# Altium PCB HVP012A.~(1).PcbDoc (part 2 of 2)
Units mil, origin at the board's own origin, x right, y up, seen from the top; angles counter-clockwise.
Board outline 2249 x 2178 mil, 4 copper layers (Top Layer, MidLayer1, MidLayer2, Bottom Layer), stack 61.2 mil thick; 92 components, 29 nets, 189 pads, 191 vias.
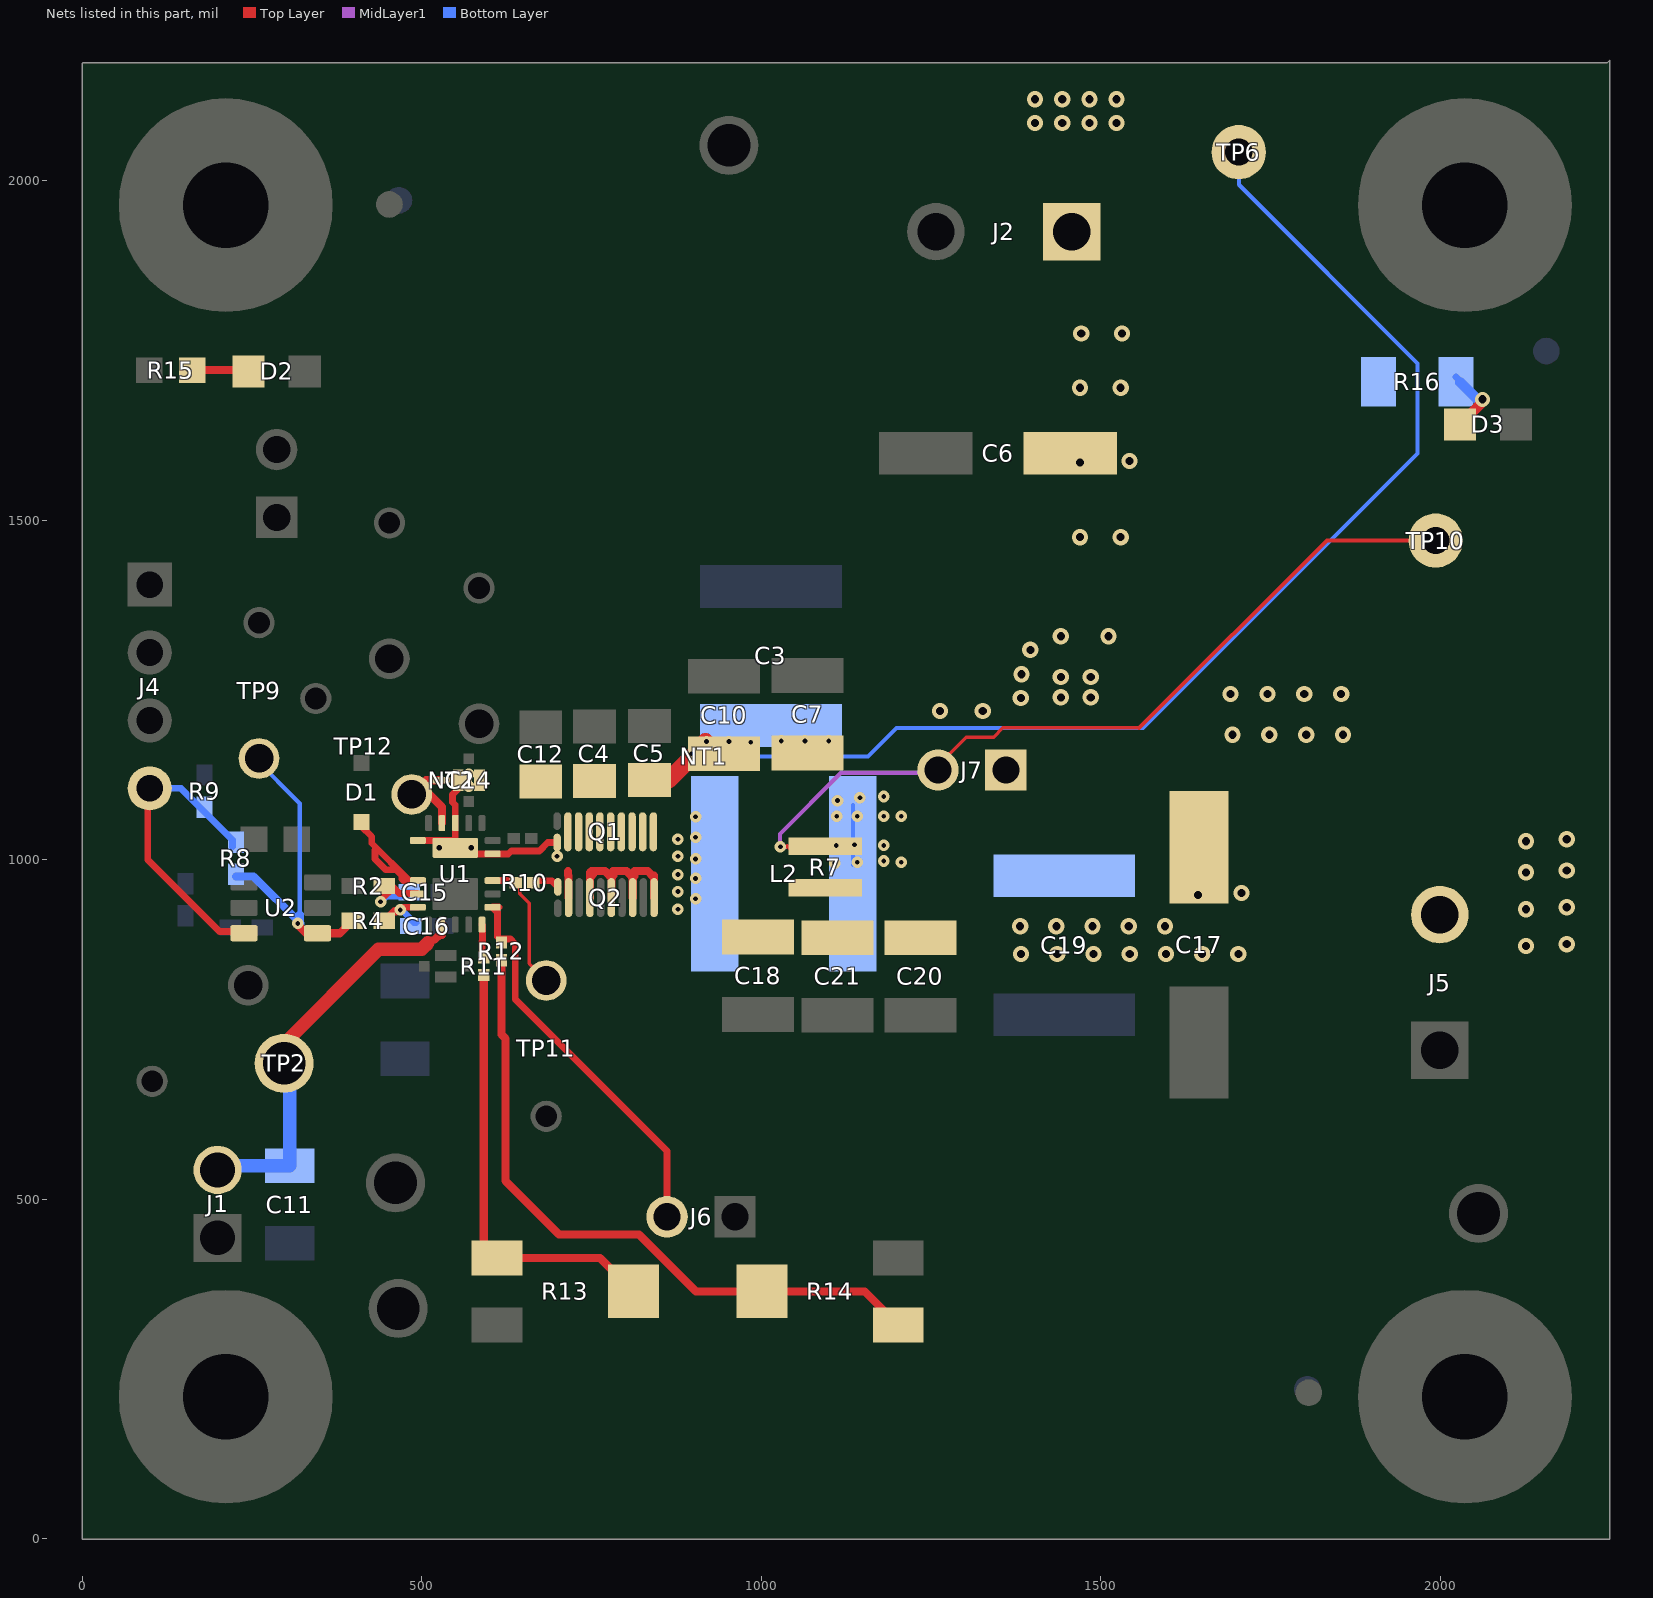
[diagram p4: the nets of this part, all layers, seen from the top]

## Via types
v1: diameter 24, hole 12, Top Layer to Bottom Layer, tented both sides, 110 vias
v2: diameter 17, hole 7, Top Layer to Bottom Layer, tented both sides, 71 vias
v3: diameter 22, hole 12, Top Layer to Bottom Layer, tented both sides, 6 vias
v4: diameter 19.68, hole 7.87, Top Layer to Bottom Layer, 4 vias

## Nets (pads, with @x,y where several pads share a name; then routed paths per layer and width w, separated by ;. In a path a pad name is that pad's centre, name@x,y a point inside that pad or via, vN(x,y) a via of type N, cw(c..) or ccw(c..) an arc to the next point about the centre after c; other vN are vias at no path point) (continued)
HS2: C14.3 L2.1 NT2.2 Q1.2 Q1.4 Q1.6 Q1.8 Q1.10 Q2.3 Q2.5 Q2.7 Q2.9 Q2.11 U1.9 U1.13 U1.16 U1.21@549,1017.39 | length 659.3
  Top Layer w10: U1.16@493.88,1028.21 U1.21@549,1028.21 ; C14.3@553.25,1117 553.25,1104.25 545,1096 545,1084.63 549,1080.63 U1.13@549,1053.8 U1.21@549,1028.21 ; Q1.2@699.13,1025.21 685.26,1025.21 672.78,1012.73 631.73,1012.73 627,1008 626.47,1008.53 U1.9@604.12,1008.53 557.86,1008.53 U1.21@549,1017.39 U1.21@549,1028.21
  Top Layer w12: 715,983 715,977.01 715.88,976.13 Q2.3@715.88,944 ; Q2.5@747.38,944 747.38,976.13 ; Q2.7@778.87,944 778.87,976.13 ; Q2.9@810.37,944 810.37,976.13 ; Q2.11@841.87,944 841.87,976.48 841.51,976.13 839.41,976.13 832.5,983.04 812.83,983.04 812.83,976.13 810.37,976.13 ; 747.38,976.13 749.83,976.13 749.83,976.48 ; 747.38,976.13 747.73,976.48 749.83,976.48 ; 747.38,976.13 747.38,980.99 748,981.61 749.83,979.78 ; 749.83,976.48 749.83,979.78 ; 749.83,976.48 750.19,976.48 750.19,979.43 ; 749.83,979.78 749.83,983.04 750.19,983.04 ; 749.83,979.78 750.19,979.43 ; 750.19,979.43 750.19,983.04 ; 750.19,979.43 751.66,977.95 751.66,983.04 ; 750.19,983.04 751.66,983.04 ; 751.66,983.04 769.51,983.04 776.06,976.48 ; 776.06,976.48 781.33,976.48 ; 776.06,976.48 776.42,976.13 ; 776.42,976.13 778.87,976.13 ; 776.42,976.13 778.87,976.13 ; 778.87,976.13 781.33,976.13 781.33,976.48 ; 781.33,976.48 781.33,983.04 781.68,983.04 ; 781.33,976.48 781.68,976.48 781.68,983.04 ; 781.68,983.04 801.01,983.04 807.56,976.48 ; 807.56,976.48 810.37,976.48 810.37,976.13 ; 807.56,976.48 807.91,976.13 810.37,976.13
  Bottom Layer w6: v2@564,1126 v2@566,1124
  other v2: 877,927 903,942.39 877,953 903,972.39 877,978 903,1001 699,1005 877,1005 877,1030 903,1033 903,1063 569,1108 569,1126
  other v4: 525.38,1017.39 572.62,1017.39
K_VIN: NT1.2 TP6.1 | length 1773.7
  Bottom Layer w6: NT1.2@930,1152 1157,1152 1199,1194 1562,1194 1966,1598 1966,1731 1703,1994 TP6.1@1703,2042
LGATE: Q2.1 R10.2 | length 39
  Top Layer w10: R10.2@664.99,969 690.92,969 Q2.1@700.13,959.79
LO: R10.1 TP11.1 U1.8 | length 197.6
  Top Layer w5: R10.1@638.01,966 644,960.01 644,950 658,936 658,847 TP11.1@683,822
  Top Layer w10: U1.8@604.12,969.16 638.85,969.16 R10.1@639.01,969
NetC11_2: C11.2 J1.2 TP2.1 U1.2 | length 600.6
  Top Layer w10: U1.2@529.21,904.2 U1.2@529.21,904.62
  Top Layer w12: 508.8,877.39 512.42,881 ; 518.78,882.22 525.79,889.22 529.31,889.22 U1.2@529.31,904.2
  Top Layer w20: TP2.1@297,700 297,729 436,868 499.42,868 508.8,877.39
  Bottom Layer w20: J1.2@199,539 209.09,549.09 C11.2@305,549.09 305,692 TP2.1@297,700
NetC15_2: C15.2 R2.2 U1.18 | length 145.5
  Top Layer w10: v2@440,939 440,941 R2.2@458,959 ; R2.2@444.62,961 456,961 R2.2@458,959 ; 466,951 R2.2@458,959 ; 467,950 493.35,950 U1.18@493.88,949.47
  Bottom Layer w10: v2(439,938) 447,946 468.57,946 C15.2@472.57,950 ; C15.2@467,950 C15.2@472.57,950 ; C15.2@477.62,950 C15.2@472.57,950 ; C15.2@488.38,951 473.57,951 C15.2@472.57,950
NetC16_1: C16.1 R4.2 U1.19 | length 92.4
  Top Layer w10: R4.2@444.62,910 459.62,925 462,922.62 465,925.62 v2@465,927 ; v2@469,926 472.79,929.79 U1.19@493.88,929.79
  Bottom Layer w10: v2@465,923.32 v2@465,927 ; v2@468,928 489,907 C16.1@491.38,907
  other v2: 468,926
NetD1_2: D1.2 U1.17 | length 189.4
  Top Layer w10: D1.2@410,1049.8 426,1033.8 426,1024.16 481,969.16 472.71,969.16 470.37,971.5 470.37,976.95 462.32,985 447,985 431,1001 431,1014
NetD2_1: D2.1 R15.2 | length 79.7
  Top Layer w12: R15.2@161.5,1721 232.66,1721 D2.1@238.66,1715
NetD3_1: D3.1 R16.2 | length 100.9
  Top Layer w10: v3@2060,1678 v3(2062,1678)
  Top Layer w15: D3.1@2028.66,1641 v3@2060,1672.34
  Bottom Layer w10: R16.2@2023.09,1711 2030,1704.09 R16.2@2029,1703.09 ; v3@2054.09,1678 v3(2062,1678)
  Bottom Layer w15: R16.2@2029,1703.09 v3@2054.09,1678
NetJ6_2: J6.2 R12.2 U1.6 | length 582.1
  Top Layer w10: U1.6@604.01,930.21 U1.6@612.92,930.21 ; R12.2@611.42,886.58 611.42,922.48 U1.6@604.12,929.79 U1.6@613.26,929.79 ; R12.2@617,882.96 630.24,882.96 637.24,875.96 637.24,794.52 861,570.75 J6.2@861,474
NetJ7_2: J7.2 L2.2 R7.1 TP10.1 | length 1282.8
  Top Layer w5: v2(1028,1019) 1036.49,1019 1037.74,1020.26 R7.1@1041,1017 ; J7.2@1260,1132 1253,1132 1301.5,1180.5 1341.95,1180.5 1355.45,1194 1556.02,1194
  Top Layer w6: 1556.02,1194 1832.71,1470 TP10.1@1993,1470
  MidLayer1 w6: v2@1035,1018 1027,1026 1027,1038 1117,1128 J7.2@1259,1128
  Bottom Layer w6: L2.2@1134.57,992 1134.57,1022 L2.2@1134.57,1080.57
  other v2: 1108,995 1141,996 1206,996 1180,998 1110,1021 1180,1021 1137,1022 1111,1064 1141,1064 1180,1064 1206,1064 1112,1087 1145,1091 1180,1093
NetNT2_1: NT2.1 TP12.1 U1.14 | length 128.5
  Top Layer w12: NT2.1@529,1117 506,1117 TP12.1@485,1096 511,1096 529.31,1077.69 U1.14@529.31,1053.8
NetR11_1: R11.1 R13.1 R13.2 | length 644.1
  Top Layer w12: R11.1@591,828.04 591,432.82 R13.1@610.61,413.21 762.18,413.21 R13.2@811.39,364
NetR11_2: R11.2 U1.5 | length 47.8
  Top Layer w10: U1.5@588.37,904.2 589,903.57 589,879.66 588.37,879.03 588.37,860.59 R11.2@591,857.96
NetR12_1: R12.1 R14.1 R14.2 | length 994.8
  Top Layer w12: R12.1@617,853.04 617,742.32 623,736.32 623,527 702,448 819.72,448 903.72,364 R14.2@1000.61,364 1152.18,364 R14.1@1201.39,314.79
PWM: R4.1 R8.2 TP9.1 U2.4 | length 491.9
  Top Layer w12: v2@316,905 329.4,891.6 U2.4@346.13,891.6 378.98,891.6 R4.1@397.38,910
  Bottom Layer w6: TP9.1@254,1149 320,1083 320,919
  Bottom Layer w12: R8.2@226,975.38 251.91,975.38 v2@320,907.28 ; v2(317,906) 321.28,906 v2@320,907.28 ; 320,919 v2@320,907.28
PWM_IN: J4.4 R8.1 R9.2 U2.3 | length 449.2
  Top Layer w10: J4.4@96,1099 96,1000 202,894 235.46,894 U2.3@237.87,891.6
  Bottom Layer w10: J4.4@99,1105 145,1105 221,1029 R8.1@221,1019
VIN: C3.1 C4.1 C5.1 C6.1 C7.1 C10.1 C12.1 J2.1 NT1.1 Q1.3 Q1.5 Q1.7 Q1.9 Q1.11 R16.1 | length 110.8
  Top Layer w10: C5.1@835,1117 863.12,1117 C5.1@866,1117
  Top Layer w25: C5.1@863.12,1117 917.41,1171.29 C10.1@917.41,1174.32
  other v1: 1263,1219 1326,1219 1382,1238 1441,1239 1485,1239 1441,1269 1485,1269 1383,1273 1396,1309 1441,1329 1511,1329 1469,1475 1529,1475 1469,1585 1542,1587 1469,1695 1529,1695 1471,1775 1531,1775 1403,2085 1443,2085 1483,2085 1523,2085 1403,2120 1443,2120 1483,2120 1523,2120
  other v2: 897.07,1155.9 984.07,1172.9 919.07,1173.9 952.07,1173.9 1029.07,1174.9 1064.07,1174.9 1099.07,1174.9
VOUT: C17.1 C18.1 C19.1 C20.1 C21.1 J5.2 J7.1 R7.2
  other v1: 1382.33,861 1435.67,861 1489,861 1542.33,861 1595.67,861 1649,861 1702.33,861 2126,872.71 2186,875.57 1381,902 1434.33,902 1487.67,902 1541,902 1594.33,902 2126,927 2186,929.86 1642.67,948 1707,951 2126,981.29 2186,984.14 2126,1027.14 2186,1030 1693.71,1184 1748,1184 1802.29,1184 1856.57,1184 1690.86,1244 1745.14,1244 1799.43,1244 1853.71,1244
pads on no net: FID1.1 FID2.1 FID3.1 FID4.1 FID5.1 FID6.1 H1.1 H2.1 H3.1 H4.1 H5.0 H6.0 H7.0 H8.0 SH-J1.0 U1.1 U1.20@530.3,949.47 U1.20@567.7,949.47 U1.21@530.3,1017.39 U1.21@567.7,1017.39

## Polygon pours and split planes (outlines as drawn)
HS2 on Bottom Layer "HS2_L04_P014" (solid, remove dead copper, pour order 14): 912,1075 882,1045 873,1045 871,1043 871,914 912,876
GND on Bottom Layer "GND_L04_P102" (solid, remove dead copper, pour order 102): 2164.33,41.8 122.33,41.8 22.33,141.8 28.33,147.8 28.33,2075.8 28.33,2077.8 101.33,2150.8 2055.33,2150.8 2234.33,1971.8 2234.33,110.8
HS2 on Bottom Layer "HS2_L04_P078" (solid, remove dead copper, pour order 78): 520,1204 532.96,1172.96 590,1155 631,1080 704,1073 704,982.06 491.65,998 443.21,1077.98 359.33,1130.33 359.33,1204
NetJ7_2 on Bottom Layer "NETJ7_2_L04_P039" (solid, pour order 39): 1099,865 1098,864 1098,734 1106,726 1169,726 1173,730 1255,859 1249,1149 1177,1139 1098,1137
VIN on Bottom Layer "Bottom Layer-No Net 7" (solid, pour order 76): 1386.49,2144 1961,2144 1961,1563.67 1934.95,1563.67 1550.44,1194.15 1541.57,1185.62 917.42,1185.62 911,1192.28 911,1230 956.33,1230 1313.99,1304.19 1317.45,1304.19 1384.55,1368.68 1386.49,1370.54
VOUT on Bottom Layer "Bottom Layer-No Net 6" (solid, pour order 42): 1871,1479 2246,1479 2246,819.43 1256,819.43 1256,1171.3 1551.61,1171.3 1561,1169
HS2 on Bottom Layer "HS2_L04_P104" (solid, remove dead copper, pour order 104): 866,914 926,914 926,1074 921,1079 866,1079
HS2 on Bottom Layer "HS2_L04_P022" (solid, pour order 22): 895,898 895,732 899,728 960,728 966,734 966,834 964,836 964,902
HS2 on MidLayer1 "HS2_L02_P016" (solid, remove dead copper, pour order 16): 520,1204 532.96,1172.96 590,1155 631,1080 704,1073 704,982.06 491.65,998 443.21,1077.98 359.33,1130.33 359.33,1204
GND on MidLayer1 "GND_L02_P082" (solid, remove dead copper, pour order 82): 2154,39 112,39 12,139 18,145 18,2073 18,2075 91,2148 2045,2148 2224,1969 2224,108
HB2 on Top Layer "HB2_L01_P092" (solid, remove dead copper, pour order 92): 582,1138 553,1109 425,1109 392,1142 392,1157 424,1189 427,1192 531,1192 554,1169 573,1169 573,1167 587,1153
NetD1_2 on Top Layer "NETD1_2_L01_P090" (solid, remove dead copper, pour order 90): 386.5,1035.5 427,995 461,961 496,961 503,968 503,978 459,1019 435,1070 392,1070 390,1072
LGATE on Top Layer "LGATE_L01_P023" (solid, pour order 23): 656,974 656,944 661,939 671,929 699.35,929 701,929 706,934 704,976 659.22,977.22
HGATE on Top Layer "HGATE_L01_P024" (solid, pour order 24): 653,1024 654.21,1025.21 701,1025.21 701,1074 667,1074 652,1059 652,1039
HS2 on Top Layer "HS2_L01_P059" (solid, remove dead copper, pour order 59): 628.05,1033.74 859.92,1044.98 900,1065 913,1060.46 913,893.02 882.19,910 820.48,944 624.53,947.6
GND on Top Layer "Top Layer-No Net 1" (solid, pour order 28): 386,2040 870.39,2040 870.39,2151 1361,2151 1361,1442.42 1090.76,1249.76 866.37,1235.5 858,1171 641,1171 641,1299 386,1684
GND on Top Layer "Top Layer-No Net 9" (solid, remove dead copper, pour order 49): 31,779 518.78,882.22 1315.36,266.34 1724,266.34 1724,-1 31,-1
VOUT on Top Layer "Top Layer-No Net 2" (solid, pour order 27): 2201,1479 1871,1479 1561,1169 1541,1169 1277,1169 1246,969 946,969 946,859 2201,842
VIN on Top Layer "Top Layer-No Net" (solid, pour order 29): 1381,2152 1381,1438.77 1239.07,1302.37 1136.32,1247.31 888,1227 888,1165 829.3,1141.2 657,1139.05 657,1090.12 681.83,1081.42 712.65,1057 877.07,1057 967,1126 1139.79,1138.79 1309,1181 1341,1188.87 1532.38,1188.87 1853,1497 1853,2152
GND on Top Layer "Top Layer-No Net 4" (solid, pour order 35): 2253.16,344.84 2253.16,329 1304.43,317.34 675.28,735.25 676.78,942.76 805.53,944.61 986,813.05 2251.68,813.05
NetJ7_2 on Top Layer "NETJ7_2_L01_P094" (solid, remove dead copper, pour order 94): 1081,989 1216,989 1221,994 1221,1079 1216,1084 1203,1097 1089,1097 1076,1084 1076,999 1086,989
no net on Bottom Solder "NONET_L-01_P-001" (solid): 1099,865 1098,864 1098,734 1106,726 1169,726 1173,730 1173,859
no net on Bottom Solder "NONET_L-01_P-001" (solid): 902,894 902,896 864,934 821,934 820,933 820,1049 821,1048 868,1048 872,1048 896,1072 909,1072 910,1073 922,1061 922,893
no net on Bottom Solder "NONET_L-01_P-001" (solid): 896,861 895,860 895,730 903,722 966,722 970,726 970,855
no net on Bottom Paste "NONET_L-01_P-001" (solid): 1099,865 1098,864 1098,734 1106,726 1169,726 1173,730 1173,859
no net on Bottom Paste "NONET_L-01_P-001" (solid): 895,875 894,874 894,744 902,736 965,736 969,740 969,869
HS2 on MidLayer2 "HS2_L03_P015" (solid, remove dead copper, pour order 15): 520,1204 532.96,1172.96 590,1155 631,1080 704,1073 704,982.06 491.65,998 443.21,1077.98 359.33,1130.33 359.33,1204
GND on MidLayer2 "GND_L03_P017" (solid, remove dead copper, pour order 17): 2154,39 112,39 12,139 18,145 18,2073 18,2075 91,2148 2045,2148 2224,1969 2224,108

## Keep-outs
Keep-Out Layer:
  the board outline again, w25
  text ".Layer_Name" at -322,-1089.49 h60

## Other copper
Top Layer:
  rectangle net NetJ6_2: 606,919 631,929
  rectangle net HS2: 470,1024 495,1034
  text ".Layer_Name" at -322,-1089.49 h60
MidLayer1:
  pour cut-out: 871,1065 870,1066 870,1162 1193,1162 1195,1160 1195,799.35 1196.35,798 872,798 869,801 869,903 871,902.42
MidLayer2:
  pour cut-out: 871,1065 870,1066 870,1162 1193,1162 1195,1160 1195,799.35 1196.35,798 872,798 869,801 869,903 871,902.42
Bottom Layer:
  pour cut-out: 926.36,1079 870,1079 870,1162 1101,1162 1101,798 982,801 962,883 900,883 869,801 872,887.92 921,887.92
  text ".Layer_Name" at -322,-1089.49 h60

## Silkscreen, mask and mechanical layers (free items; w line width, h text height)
Top Overlay:
  lines w10: 370,836 465,741 ; 371,990 374,1172 ; 371,1160 373,1160 513,1300 ; 372,831 372,870 ; 465,735 1174,732 ; 521,1301 521,1408 524,1411 ; 521,1306 548,1306 ; 525,1414 552,1414 ; 525,1415 508,1432 508,1469 520,1481 829,1481 846,1464 846,1423 834,1411 ; 616,1412 834,1412 ; 617,1307 1068,1306 ; 1129,1299 1129,1241 1185,1185 1185,929
  text "-" at 1066,2009 h80
  text "+" at 1571,2009 h80
  text "EN(HI)" at 31,1616 h30
  text "GND" at 29.27,1569 h30
  text "GND" at 29.5,1520.46 h30 r359.79
  text "PWM(LI)" at 32,1477 h30
  text "14 x 20mm" at 521,1424 h72.83
  text "+" at 2132,1062 h80 r90
  text "-" at 2153,540 h80 r90
  text "HVP006 A" at 1380,125 h40
  text "LMG1210EVM-012" at 1330,46 h40
  text ".Layer_Name" at -322,-1089.49 h60
Bottom Overlay:
  text ".Layer_Name" at -322,-1089.49 h60
Top Paste:
  text ".Layer_Name" at -322,-1089.49 h60
Bottom Paste:
  text ".Layer_Name" at -322,-1089.49 h60
Top Solder:
  rectangle: 523,1065 536,1082
  rectangle: 543,1064 556,1081
  rectangle: 562,1066 575,1083
  region: 630,1022 630,1035 613,1035 613,1022
  region: 626,1002 626,1015 609,1015 609,1002
  region: 628,963 628,976 611,976 611,963
  region: 628,943 628,956 611,956 611,943
  region: 630,918 630,931 610,931 610,918
  region: 575,896 562,896 562,879 575,879
  region: 555,896 542,896 542,879 555,879
  region: 535.32,896 522.32,896 522.32,879 535.32,879
  region: 468,936.21 468,923.21 485,923.21 485,936.21
  region: 468,955.89 468,942.89 485,942.89 485,955.89
  region: 468,976 468,963 485,963 485,976
  region: 466,1034.21 466,1021.21 483,1021.21 483,1034.21
  text ".Layer_Name" at -322,-1089.49 h60
  text ".Layer_Name" at -322,-1089.49 h60
Bottom Solder:
  text ".Layer_Name" at -322,-1089.49 h60
Drill Guide:
  text ".Layer_Name" at -322,-1089.49 h60
M1 Board Outline:
  lines w10: 1,-1 2236,-1
  lines w25: 1,-1 0,2173 1,2174 2246,2174 2249,2177 2251,4
  text ".Layer_Name" at -322,-1089.49 h60
M2 Board Dimensions:
  rectangle: -899.5,-516.5 -774.5,-391.5
  rectangle: -774.5,-641.5 -399.5,-516.5
  lines w7: -899.5,-516.5 100.5,-516.5 ; -774.5,-641.5 -774.5,-391.5 ; -649.5,-641.5 -649.5,-391.5 ; -399.5,-641.5 -399.5,-391.5 ; -149.5,-641.5 -149.5,-391.5 ; -899.5,-641.5 100.5,-641.5 100.5,-391.5 -899.5,-391.5 -899.5,-641.5
  lines w10: -899.5,-706.5 -899.5,-686.5 ; -839.5,-716.5 -899.5,-696.5 ; -839.5,-676.5 -899.5,-696.5 ; -675.42,-696.5 -899.5,-696.5 ; -123.58,-696.5 100.5,-696.5 ; 40.5,-716.5 100.5,-696.5 ; 40.5,-676.5 100.5,-696.5 ; 100.5,-706.5 100.5,-686.5
  text "1000 (mil)" at -665.42,-732.49 h60
  text ".Layer_Name" at -322,-1089.49 h60
M3 3D STEP Top:
  text ".Layer_Name" at -322,-1089.49 h60
M4 3D STEP Bottom:
  text ".Layer_Name" at -322,-1089.49 h60
M5 Assembly Top:
  lines w10: -1191,-1161.17 5409,-1161.17 ; -1191,-957.83 5411,-957.83 ; -1191,-754.5 -1191,-1364.5 2814,-1364.5 5411,-1364.5 5411,-754.5 -1190.5,-754.5 -1190.5,-1364.5 385,-1364.5 ; 1274,-1364.5 1274,-754.5 ; 2541,-957.83 2541,-754.5 ; 3381,-957.83 3381,-754.5 ; 4003,-1371 4003,-1168.17
  text "COMPONENTS MARKED 'DNP' SHOULD NOT BE POPULATED." at 254.5,-549.5 h60
  text "ASSEMBLY VARIANT:" at 254,-665 h60
  text ".VariantName" at 1290,-665 h60
  text "PCB VIEWED FROM TOP SIDE" at -1127.5,-886.67 h60
  text "BOARD #:" at 1349,-886.67 h60
  text ".PRJ_Number" at 1894.5,-886.67 h60
  text "REV:" at 2739,-886.67 h60
  text ".PCB_Rev" at 3030.5,-886.67 h60
  text "SVN REV:" at 3577,-886.67 h60
  text ".VersionControl_RevNumber" at 4083,-886.67 h60
  text "IGNORE ->" at -1127.5,-1089.49 h60
  text "PLOT NAME =" at -1127.5,-1295.33 h60
  text ".plot_File_Name" at -322,-1295.33 h60
  text "GENERATED    :" at 1351,-1295.33 h60
  text ".Print_Date" at 2220.5,-1295.33 h60
  text ".Print_Time" at 2949.5,-1295.33 h60
  text "TEXAS INSTRUMENTS" at 4214,-1295.33 h60
M6 Assembly Bottom:
  lines w10: -1191.5,-958.33 5410.5,-958.33 ; -1189.5,-1161.67 5410.5,-1161.67 ; 216.5,-1371.5 216.5,-1168.67 ; 838.5,-958.33 838.5,-755 ; 1678.5,-958.33 1678.5,-755 ; 2945.5,-1365 2945.5,-755 ; 3834.5,-1365 5410,-1365 5410,-755 -1191.5,-755 -1191.5,-1365 1405.5,-1365 5410.5,-1365 5410.5,-755
  text "COMPONENTS MARKED 'DNP' SHOULD NOT BE POPULATED." at 5203,-549 h60
  text ".VariantName" at 4159,-665 h60
  text "ASSEMBLY VARIANT:" at 5198,-665 h60
  text ".VersionControl_RevNumber" at 136.5,-887.17 h60
  text "SVN REV:" at 642.5,-887.17 h60
  text ".PCB_Rev" at 1189,-887.17 h60
  text "REV:" at 1480.5,-887.17 h60
  text ".PRJ_Number" at 2325,-887.17 h60
  text "BOARD #:" at 2870.5,-887.17 h60
  text "PCB VIEWED FROM BOTTOM SIDE" at 5347,-887.17 h60
  text "IGNORE ->" at 1648.85,-1089.49 h60
  text "TEXAS INSTRUMENTS" at 5.5,-1295.83 h60
  text ".Print_Time" at 1270,-1295.83 h60
  text ".Print_Date" at 1999,-1295.83 h60
  text "GENERATED    :" at 2868.5,-1295.83 h60
  text ".plot_File_Name" at 4541.5,-1295.83 h60
  text "PLOT NAME =" at 5347,-1295.83 h60
M9 Title Sheet:
  drawing of 56 lines, arcs and shapes, not listed
  text "1" at -159.16,7805.5 h70
  text "2" at 2336.5,7805.5 h70
  text "3" at 4825.84,7805.5 h70
  text "4" at 7332.51,7805.5 h70
  text "5" at 9831.5,7805.5 h70
  text "A" at -1315.5,6662.5 h70
  text "A" at 13484.5,6662.5 h70
  text "B" at -1315.5,4282.5 h70
  text "B" at 13484.5,4282.5 h70
  text "C" at -1315.5,1907.5 h70
  text "C" at 13484.5,1907.5 h70
  text "PROJECT TITLE:" at 10444.5,46.5 h45
  text ".PRJ_Title" at 10494.5,-86.83 h70
  text "DESIGNED FOR:" at 10444.5,-254.5 h45
  text ".PRJ_Customer" at 10494.5,-394.5 h70
  text "D" at -1315.5,-462.5 h70
  text "D" at 13484.5,-462.5 h70
  text "FILE NAME:" at 10444.5,-554.5 h45
  text ".PCB_File_Name_No_Path" at 10494.5,-674.5 h70
  text "Texas Instruments (TI) and/or its licensors do not warrant the accuracy or completeness of this specification" at 5475,-836.34 h45
  text "ENGINEER:" at 10444.5,-844.5 h45
  text "LAYOUT BY:" at 11949.5,-844.5 h45
  text "or any information contained therein. TI and/or its licensors do not warrant that this design will meet" at 5430.01,-949 h45
  text "Narendra Mehta" at 10494.5,-999.49 h70
  text "Narendra Mehta" at 12000,-999.49 h70
  text "the specifications, will be suitable for your application or fit for any particular purpose, or will operate in" at 5430.01,-1061.67 h45
  text ".Layer_Name" at -322,-1089.49 h60
  text "ALTIUM DESIGNER VERSION:" at 11949.5,-1154.5 h45
  text "an implementation. TI and/or its licensors do not warrant that the design is production worthy. You should" at 5430.01,-1174.33 h45
  text "completely validate and test your design implementation to confirm the system functionality for your application." at 5475,-1287 h45
  text ".print_Scale" at 10494.5,-1287.83 h70
  text ".Application_BuildNumber" at 12000,-1287.83 h70
  text "1" at -159.16,-1494.5 h70
  text "2" at 2336.5,-1494.5 h70
  text "3" at 4825.84,-1494.5 h70
  text "4" at 7332.51,-1494.5 h70
  text "5" at 9831.5,-1494.5 h70
  text "6" at 12336.5,-1494.5 h70
M10 Fab Notes:
  drawing of 212 lines, arcs and shapes, not listed
  text "DESIGN INFORMATION" at 11494.02,6928 h60
  text "(REFER ALSO ARRAY/PANEL PROFILING INFORMATION)" at 11132.46,6766.29 h60
  text "BOARD SIZE" at 10446.46,6762 h60
  text "2175MIL" at 10908.78,6634.18 h60
  text "X" at 11414.46,6634.18 h60
  text "2250" at 11645.78,6634.18 h60
  text "Number of Layers :" at 10849.46,6437 h60
  text "4" at 11944.27,6427 h60
  text "MIN. TRACK WIDTH:" at 10849.46,6298 h60
  text "5" at 11945.7,6298 h60
  text "MIL" at 12100.46,6298 h60
  text "MIN. CLEARANCE:" at 10849.46,6166 h60
  text "4" at 11945.7,6166 h60
  text "MIL" at 12100.46,6166 h60
  text "MIN. VIA PAD SIZE:" at 10849.46,6034 h60
  text "18" at 11915.71,6034 h60
  text "MIL" at 12100.46,6034 h60
  text "0.05mm (2MIL)" at 11544.46,5892.29 h60
  text "MINIMUM ANNULAR RING" at 10520.23,5888.01 h60
  text "EXTERNAL" at 12252.46,5888.01 h60
  text "PER" at 10720.23,5770 h60
  text "IPC-D-275 CLASS 2 LEVEL C" at 10940.23,5770 h60
  text "MIL, HOLES" at 12428.46,5657.71 h60
  text "+/-" at 12036,5657 h60
  text "+/-" at 12890,5657 h60
  text "REGISTRATION TOLERANCES:" at 10520.23,5652 h60
  text "METAL" at 11720,5652 h60
  text "5" at 12296.2,5652 h60
  text "3" at 13129.2,5652 h60
  text "MIL" at 13245.46,5652 h60
  text "NOTE:  Fill vias and plate shut then polish flat." at 10524.4,5428.4 h120
  text "MATERIAL:" at 10433.46,5093.54 h60
  text "FR-4 High Tg" at 11419.9,4953.21 h60
  text "FR-408" at 10854.46,4944.64 h60
  text "X" at 11266.46,4944.64 h60
  text "OTHER" at 12342.46,4944.64 h60
  text "62 MIL (1.6mm) +/-10%" at 11174.56,4781.92 h60
  text "THICKNESS:" at 10508.23,4777.64 h60
  text "X" at 11046.4,4777.64 h60
  text "OTHER" at 12459.46,4777.64 h60
  text "TOLERANCE:" at 10508.23,4619.64 h60
  text "X" at 11347.53,4619.64 h60
  text "ANSI IPC-6012 TYPE 3 CLASS 2" at 11534.48,4619.64 h60
  text "OTHER +/-" at 11534.46,4463.64 h60
  text "BOW & TWIST:" at 10508.23,4306.64 h60
  text "X" at 11347.53,4306.64 h60
  text "ANSI IPC-6012 TYPE 3 CLASS 2" at 11534.48,4306.64 h60
  text "OTHER +/-" at 11534.46,4148.13 h60
  text "COPPER THICKNESS (FINISHED):" at 10433.46,4012.64 h60
  text "1.4MIL (1oz)" at 11313.46,3859.92 h60
  text "2MIL (1.4oz)" at 12080.46,3859.92 h60
  text "2.8MIL (2oz)" at 12807.46,3859.92 h60
  text "OUTER:" at 10790.46,3855.64 h60
  text "X" at 12701,3849 h60
  text "X" at 11951,3719 h60
  text "1.4MIL (1oz)" at 11313.46,3702.92 h60
  text "2.8MIL (2oz)" at 12080.46,3702.92 h60
  text "N/A" at 12807,3703.29 h60
  text "INNER SIGNAL:" at 10501.38,3698.64 h60
  text "DRILLING:" at 10433.46,3559.64 h60
  text "REFERENCE:" at 10508.23,3442.64 h60
  text "X" at 11156.46,3442.64 h60
  text "AS SHOWN" at 11343.46,3442.64 h60
  text "X" at 12057.46,3442.64 h60
  text "NC_DRILL FILES" at 12194.46,3442.64 h60
  text "PTH MIN COPPER THICKNESS:" at 10508.23,3284.64 h60
  text "X" at 11858.46,3284.64 h60
  text "1MIL" at 11995.46,3284.64 h60
  text "OTHER" at 12492.46,3284.64 h60
  text "FAB NOTE:  Fill all in-pad vias and plate shut then polish flat." at -873,3189 h90
  text "BOARD FINISH:" at 10433.46,3125.64 h60
  text "SILKSCREEN:" at 10588.68,3007.64 h60
  text "X" at 11537.46,3007.64 h60
  text "TOP" at 11663.46,3007.64 h60
  text "X" at 12047.46,3007.64 h60
  text "BOTTOM" at 12174.46,3007.64 h60
  text "SILKSCREEN COLOR:" at 10588.68,2840.64 h60
  text "X" at 11536.42,2840.64 h60
  text "WHITE" at 11663.46,2840.64 h60
  text "OTHER" at 12174.46,2840.64 h60
  text "SOLDER RESIST COLOR:" at 10588.68,2670.64 h60
  text "X" at 11156.42,2511.44 h60
  text "GREEN" at 11283.46,2511.44 h60
  text "BLUE" at 11874.46,2511.44 h60
  text "OTHER" at 12412.46,2511.44 h60
  text "IMMERSION GOLD (ENIG)" at 11494.46,2322.92 h60
  text "ENEPIG" at 12832,2319.64 h60
  text "SURFACE FINISH:" at 10433.46,2318.64 h60
  text "X" at 11307.51,2318.64 h60
  text "IMM. TIN/SILVER OR EQUIV" at 10763,2161.64 h60
  text "OTHER" at 12194.46,2161.64 h60
  text "ARRAY/PANEL:" at 10433.46,1982.64 h60
  text "CUT AND TRIM PER MECH LAYER 1" at 11494.46,1978.35 h60
  text "N.C. ROUTE" at 11494.46,1826.64 h60
  text "X" at 12173.46,1826.64 h60
  text "V. SCORE" at 12360.46,1826.64 h60
  text "CERTIFICATION:" at 10433.46,1689.64 h60
  text "MATERIALS AND WORKMANSHIP FOR ALL PCBS" at 11158.46,1689.64 h60
  text "TO MEET OR EXCEED THE REQUIREMENTS OF:" at 11158.46,1591.64 h60
  text "X" at 10784.96,1455.14 h60
  text "ANSI IPC-A-600F CLASS ->" at 10923.96,1455.14 h60
  text "X" at 12563.02,1455.14 h60
  text "2" at 12681.96,1455.14 h60
  text "1" at 12366.96,1453.64 h60
  text "3" at 13035.96,1453.64 h60
  text "X" at 10787.02,1295.64 h60
  text "UL 94V-0" at 10923.96,1295.64 h60
  text "X" at 11599.02,1295.64 h60
  text "RoHS" at 11735.96,1295.64 h60
  text "OTHER" at 12380.36,1295.64 h60
  text "PER ORDER" at 12777.42,1295.64 h60
  text "ADDITIONAL REQUIREMENTS:" at 10433.46,1154.64 h60
  text "MICROSECTION:" at 10508.23,1039.64 h60
  text "YES" at 11413.96,1039.64 h60
  text "REQUIRED" at 12275.46,883.5 h60
  text "BARE BOARD ELEC. TEST:" at 10508.23,880.64 h60
  text "NONE" at 11813.96,880.64 h60
  text "X" at 12148.46,880.64 h60
  text "PER ORDER" at 12867.46,880.64 h60
  text "MANUFACTURER'S UL:" at 10508.23,723.64 h60
  text "RAIL" at 11673.96,719.35 h60
  text "METAL" at 12165.77,719.35 h60
  text "X" at 12541,719 h60
  text "SILK" at 12677.46,719.35 h60
  text ".Layer_Name" at -322,-1089.49 h60
M11 Gerber Information:
  lines w10: -1191,-1161.17 5409,-1161.17 ; -1191,-957.83 5411,-957.83 ; -1191,-754.5 -1191,-1364.5 2814,-1364.5 5411,-1364.5 5411,-754.5 -1190.5,-754.5 -1190.5,-1364.5 385,-1364.5 ; 1274,-1364.5 1274,-754.5 ; 2541,-957.83 2541,-754.5 ; 3381,-957.83 3381,-754.5 ; 4003,-1371 4003,-1168.17
  text "ALL ARTWORK VIEWED FROM TOP SIDE" at -1127.5,-886.67 h60
  text "BOARD #:" at 1349,-886.67 h60
  text ".PRJ_Number" at 1894.5,-886.67 h60
  text "REV:" at 2739,-886.67 h60
  text ".PCB_Rev" at 3030.5,-886.67 h60
  text "SVN REV:" at 3577,-886.67 h60
  text ".VersionControl_RevNumber" at 4083,-886.67 h60
  text "LAYER NAME =" at -1127.5,-1089.49 h60
  text "PLOT NAME =" at -1127.5,-1295.33 h60
  text ".plot_File_Name" at -322,-1295.33 h60
  text "GENERATED    :" at 1351,-1295.33 h60
  text ".Print_Date" at 2220.5,-1295.33 h60
  text ".Print_Time" at 2949.5,-1295.33 h60
  text "TEXAS INSTRUMENTS" at 4214,-1295.33 h60
M12 Stackup:
  drawing of 295 lines, arcs and shapes, not listed
  text "Layer" at 5497.74,6904 h60
  text "Name" at 5907.65,6904 h60
  text "Material" at 6837.4,6904 h60
  text "Thickness" at 7697.16,6904 h60
  text "Constant" at 8347,6904 h60
  text "Board Layer Stack" at 8916.86,6904 h60
  text "1" at 5497.74,6784 h60
  text "Top Overlay" at 5907.65,6784 h60
  text "2" at 5497.74,6664 h60
  text "Top Solder" at 5907.65,6664 h60
  text "Solder Resist" at 6837.4,6664 h60
  text "0.40mil" at 7697.16,6664 h60
  text "3.5" at 8347,6664 h60
  text "3" at 5497.74,6544 h60
  text "Top Layer" at 5907.65,6544 h60
  text "Copper" at 6837.4,6544 h60
  text "2.80mil" at 7697.16,6544 h60
  text "4" at 5497.74,6424 h60
  text "Dielectric1" at 5907.65,6424 h60
  text "FR-4" at 6837.4,6424 h60
  text "5.00mil" at 7697.16,6424 h60
  text "4.2" at 8347,6424 h60
  text "5" at 5497.74,6304 h60
  text "MidLayer1" at 5907.65,6304 h60
  text "Copper" at 6837.4,6304 h60
  text "2.80mil" at 7697.16,6304 h60
  text "6" at 5497.74,6184 h60
  text "Dielectric2" at 5907.65,6184 h60
  text "FR-4" at 6837.4,6184 h60
  text "40.00mil" at 7697.16,6184 h60
  text "4.2" at 8347,6184 h60
  text "7" at 5497.74,6064 h60
  text "MidLayer2" at 5907.65,6064 h60
  text "Copper" at 6837.4,6064 h60
  text "2.80mil" at 7697.16,6064 h60
  text "8" at 5497.74,5944 h60
  text "Dielectric 3" at 5907.65,5944 h60
  text "5.00mil" at 7697.16,5944 h60
  text "4.2" at 8347,5944 h60
  text "9" at 5497.74,5824 h60
  text "Bottom Layer" at 5907.65,5824 h60
  text "Copper" at 6837.4,5824 h60
  text "2.80mil" at 7697.16,5824 h60
  text "10" at 5497.74,5704 h60
  text "Bottom Solder" at 5907.65,5704 h60
  text "Solder Resist" at 6837.4,5704 h60
  text "0.40mil" at 7697.16,5704 h60
  text "3.5" at 8347,5704 h60
  text "11" at 5497.74,5584 h60
  text "Bottom Overlay" at 5907.65,5584 h60
  text ".Layer_Name" at -322,-1089.49 h60
M13 Component Bodies Top:
  text ".Layer_Name" at -322,-1089.49 h60
M14 Component Bodies Bottom:
  text ".Layer_Name" at -322,-1089.49 h60
M15 Courtyards Top:
  text ".Layer_Name" at -322,-1089.49 h60
M16 Courtyards Bottom:
  text ".Layer_Name" at -322,-1089.49 h60
Drill Drawing:
  circle w10: c4244.72,2183.32 r27.63
  circle w10: c4244.72,1561.72 r16.58
  circle w10: c4244.72,1561.72 r27.63
  lines w10: 4217.09,1285.46 4244.72,1299.27 4272.34,1285.46 4258.53,1313.08 4272.34,1340.71 4244.72,1326.9 4217.09,1340.71 4230.9,1313.08 4217.09,1285.46 ; 4217.09,1672.23 4230.9,1672.23 4230.9,1658.42 4258.53,1658.42 4258.53,1672.23 4272.34,1672.23 4272.34,1699.86 4258.53,1699.86 4258.53,1713.67 4230.9,1713.67 4230.9,1699.86 4217.09,1699.86 4217.09,1672.23 ; 4217.09,1796.55 4230.9,1796.55 4244.72,1782.74 4258.53,1796.55 4272.34,1796.55 4258.53,1810.36 4272.34,1824.18 4258.53,1824.18 4244.72,1837.99 4230.9,1824.18 4217.09,1824.18 4230.9,1810.36 4217.09,1796.55 ; 4217.09,1920.87 4230.9,1920.87 4230.9,1907.06 4258.53,1907.06 4258.53,1920.87 4272.34,1920.87 4272.34,1948.5 4258.53,1948.5 4258.53,1962.31 4230.9,1962.31 4230.9,1948.5 4217.09,1948.5 4217.09,1920.87 ; 4217.09,2045.19 4230.9,2045.19 4244.72,2031.38 4258.53,2045.19 4272.34,2045.19 4258.53,2059 4272.34,2072.82 4258.53,2072.82 4244.72,2086.63 4230.9,2072.82 4217.09,2072.82 4230.9,2059 4217.09,2045.19 ; 4217.09,2404.34 4272.34,2404.34 4272.34,2459.59 4217.09,2459.59 4217.09,2404.34 ; 4217.09,2583.91 4272.34,2583.91 4244.72,2528.66 4217.09,2583.91 ; 4228.14,1296.51 4244.72,1304.79 4261.29,1296.51 4253.01,1313.08 4261.29,1329.66 4244.72,1321.37 4228.14,1329.66 4236.43,1313.08 4228.14,1296.51 ; 4228.14,1926.39 4236.43,1926.39 4236.43,1918.11 4253.01,1918.11 4253.01,1926.39 4261.29,1926.39 4261.29,1942.97 4253.01,1942.97 4253.01,1951.26 4236.43,1951.26 4236.43,1942.97 4228.14,1942.97 4228.14,1926.39 ; 4228.14,2050.71 4236.43,2050.71 4244.72,2042.43 4253.01,2050.71 4261.29,2050.71 4253.01,2059 4261.29,2067.29 4253.01,2067.29 4244.72,2075.58 4236.43,2067.29 4228.14,2067.29 4236.43,2059 4228.14,2050.71
  lines w12: 4167,1248.16 7398.49,1248.16 ; 4167,2615.68 7398.49,2615.68 ; 4504.86,1123.84 4504.86,2740 ; 4836.86,1123.84 4836.86,2740 ; 5473.43,1123.84 5473.43,2740 ; 5732.57,1123.84 5732.57,2740 ; 6107.72,1123.84 6107.72,2740 ; 6832.05,1123.84 6832.05,2740 ; 4167,1123.84 7398.49,1123.84 7398.49,2740 4167,2740 4167,1123.84
  text "Symbol" at 4241.59,2652.98 h72
  text "Quantity" at 4542.16,2652.98 h72
  text "Finished Hole Size" at 4874.16,2652.98 h72
  text "Plated" at 5510.72,2652.98 h72
  text "Hole Type" at 5769.86,2652.98 h72
  text "Drill Layer Pair" at 6145.02,2652.98 h72
  text "Hole Tolerance" at 6869.35,2652.98 h72
  text "71" at 4542.16,2528.66 h60
  text "7.00mil (0.178mm)" at 4874.16,2528.66 h60
  text "PTH" at 5510.72,2528.66 h60
  text "Round" at 5769.86,2528.66 h60
  text "Top Layer - Bottom Layer" at 6145.02,2528.66 h60
  text "4" at 4542.16,2404.34 h60
  text "7.87mil (0.200mm)" at 4874.16,2404.34 h60
  text "PTH" at 5510.72,2404.34 h60
  text "Round" at 5769.86,2404.34 h60
  text "Top Layer - Bottom Layer" at 6145.02,2404.34 h60
  text "116" at 4542.16,2280.02 h60
  text "12.00mil (0.305mm)" at 4874.16,2280.02 h60
  text "PTH" at 5510.72,2280.02 h60
  text "Round" at 5769.86,2280.02 h60
  text "Top Layer - Bottom Layer" at 6145.02,2280.02 h60
  text "A" at 4216.31,2270.02 h55.25
  text "6" at 4542.16,2155.7 h60
  text "32.00mil (0.813mm)" at 4874.16,2155.7 h60
  text "PTH" at 5510.72,2155.7 h60
  text "Round" at 5769.86,2155.7 h60
  text "Top Layer - Bottom Layer" at 6145.02,2155.7 h60
  text "4" at 4542.16,2031.38 h60
  text "39.37mil (1.000mm)" at 4874.16,2031.38 h60
  text "PTH" at 5510.72,2031.38 h60
  text "Round" at 5769.86,2031.38 h60
  text "Top Layer - Bottom Layer" at 6145.02,2031.38 h60
  text "8" at 4542.16,1907.06 h60
  text "40.00mil (1.016mm)" at 4874.16,1907.06 h60
  text "PTH" at 5510.72,1907.06 h60
  text "Round" at 5769.86,1907.06 h60
  text "Top Layer - Bottom Layer" at 6145.02,1907.06 h60
  text "6" at 4542.16,1782.74 h60
  text "42.00mil (1.067mm)" at 4874.16,1782.74 h60
  text "PTH" at 5510.72,1782.74 h60
  text "Round" at 5769.86,1782.74 h60
  text "Top Layer - Bottom Layer" at 6145.02,1782.74 h60
  text "2" at 4542.16,1658.42 h60
  text "51.18mil (1.300mm)" at 4874.16,1658.42 h60
  text "PTH" at 5510.72,1658.42 h60
  text "Round" at 5769.86,1658.42 h60
  text "Top Layer - Bottom Layer" at 6145.02,1658.42 h60
  text "4" at 4542.16,1534.1 h60
  text "55.12mil (1.400mm)" at 4874.16,1534.1 h60
  text "PTH" at 5510.72,1534.1 h60
  text "Round" at 5769.86,1534.1 h60
  text "Top Layer - Bottom Layer" at 6145.02,1534.1 h60
  text "5" at 4542.16,1409.78 h60
  text "63.00mil (1.600mm)" at 4874.16,1409.78 h60
  text "PTH" at 5510.72,1409.78 h60
  text "Round" at 5769.86,1409.78 h60
  text "Top Layer - Bottom Layer" at 6145.02,1409.78 h60
  text "D" at 4216.31,1399.79 h55.25
  text "4" at 4542.16,1285.46 h60
  text "125.98mil (3.200mm)" at 4874.16,1285.46 h60
  text "PTH" at 5510.72,1285.46 h60
  text "Round" at 5769.86,1285.46 h60
  text "Top Layer - Bottom Layer" at 6145.02,1285.46 h60
  text "230 Total" at 4542.16,1161.14 h60
  text ".Layer_Name" at -322,-1089.49 h60

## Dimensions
2,-12 to 2252,-29 on M2 Board Dimensions
-2,-2 to -2,2172 on M2 Board Dimensions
